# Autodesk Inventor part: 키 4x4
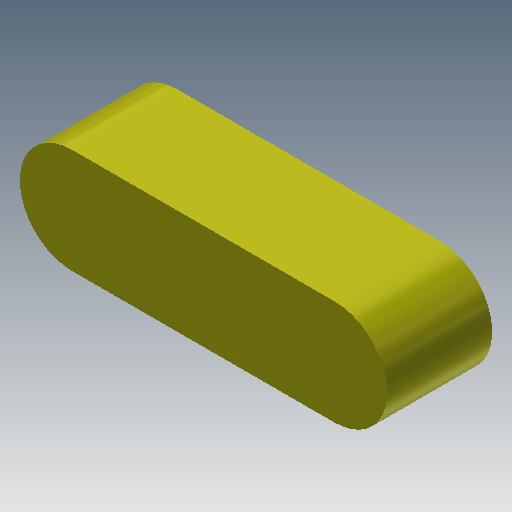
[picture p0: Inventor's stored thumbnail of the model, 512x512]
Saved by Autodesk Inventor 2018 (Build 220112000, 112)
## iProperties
Created: 2018-09
Part Number: 키 4x4
Document SubType Name: Modeling
Density: 7.86 g/cm^3
Material: 강철, 연강
Mass: 1.65269 g
Surface Area: 2.35398 cm^2
Volume: 0.210265 cm^3
Appearance: 노란색
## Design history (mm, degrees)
sketch "스케치1"
  geometry: L1 (-5, -2)-(5, -2); L2 (5, 2)-(-5, 2); A1 r 2 centre (5, 0) between (5, -2) and (5, 2); A2 r 2 centre (-5, 0) between (-5, 2) and (-5, -2); 2 further points
  constraints: 4 end point, 4 point on circle, 4 tangent, 2 centre point, 1 horizontal, 1 horizontal alignment, 1 midpoint, 1 parallel, 1 vertical alignment
  dimensions: "d0" = 4 distance between parallel lines of L1 L2; "d1" = 14 dimension on A1 A2
extrude "돌출1" new body sketch "스케치1" stored distance "d2" = 4; taper "d3" = 0 deg
node "솔리드1"
